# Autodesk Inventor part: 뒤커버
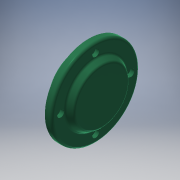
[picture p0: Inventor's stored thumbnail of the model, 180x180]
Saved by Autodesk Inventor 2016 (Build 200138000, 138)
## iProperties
Created: 2015-11
Part Number: 뒤커버
Material: 알루미늄 6061
Document SubType Name: Modeling
Designer: mduedu
Density: 2.71 g/cm^3
Mass: 309.117 g
Surface Area: 231.216 cm^2
Volume: 114.065 cm^3
Appearance: 매끄러움 - 짙은 바다 녹색
Author: mduedu
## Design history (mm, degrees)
sketch "스케치1"
  geometry: C1 r 50 at (0, 0); 1 further point
  constraints: 1 centre point, 1 coincident
  dimensions: "d42" = 100 diameter of C1
extrude "돌출1" new body sketch "스케치1" distance "d3" = 8; taper "d4" = 0 deg
sketch "스케치2"
  geometry: C1 r 35 at (0, 0); 1 further point
  constraints: 1 centre point, 1 coincident
  dimensions: "d5" = 70 diameter of C1
extrude "돌출2" join sketch "스케치2" distance "d6" = 7; taper "d7" = -30 deg
sketch "스케치5" dims "d44" = 80
  geometry: 3 further points
  constraints: 2 vertical alignment, 1 coincident, 2 other
hole "구멍3" sketch "스케치5" at (0, 40) diameter "d45" = 4.5; stored, may be unused: countersink angle "d49" = 90 deg, drill point angle "d51" = 118 deg; dims "d46" = 6, "d47" = 8, "d48" = 4.4, "d50" = 8
sketch "스케치4"
  geometry: C1 r 35 at (0, 0); 1 further point
  constraints: 1 centre point, 1 coincident
  dimensions: "d21" = 70 diameter of C1
extrude "돌출3" join sketch "스케치4" distance "d23" = 12; taper "d24" = 0 deg
hole "구멍2" diameter "d27" = 30; stored, may be unused: countersink angle "d31" = 90 deg, drill point angle "d33" = 0 deg; dims "d25" = 10, "d26" = 10, "d28" = 6, "d29" = 40, "d30" = 12, "d32" = 15
fillet "모깎기3" dims "d36" = 3
fillet "모깎기4" dims "d37" = 3
fillet "모깎기5" dims "d38" = 0.3
chamfer "모따기1" distance "d39" = 1; stored, may be unused: second distance "d40" = 2, angle "d41" = 45 deg
node "솔리드1"
pattern_circular "원형 패턴2" dims angle "d53" = 360 deg
